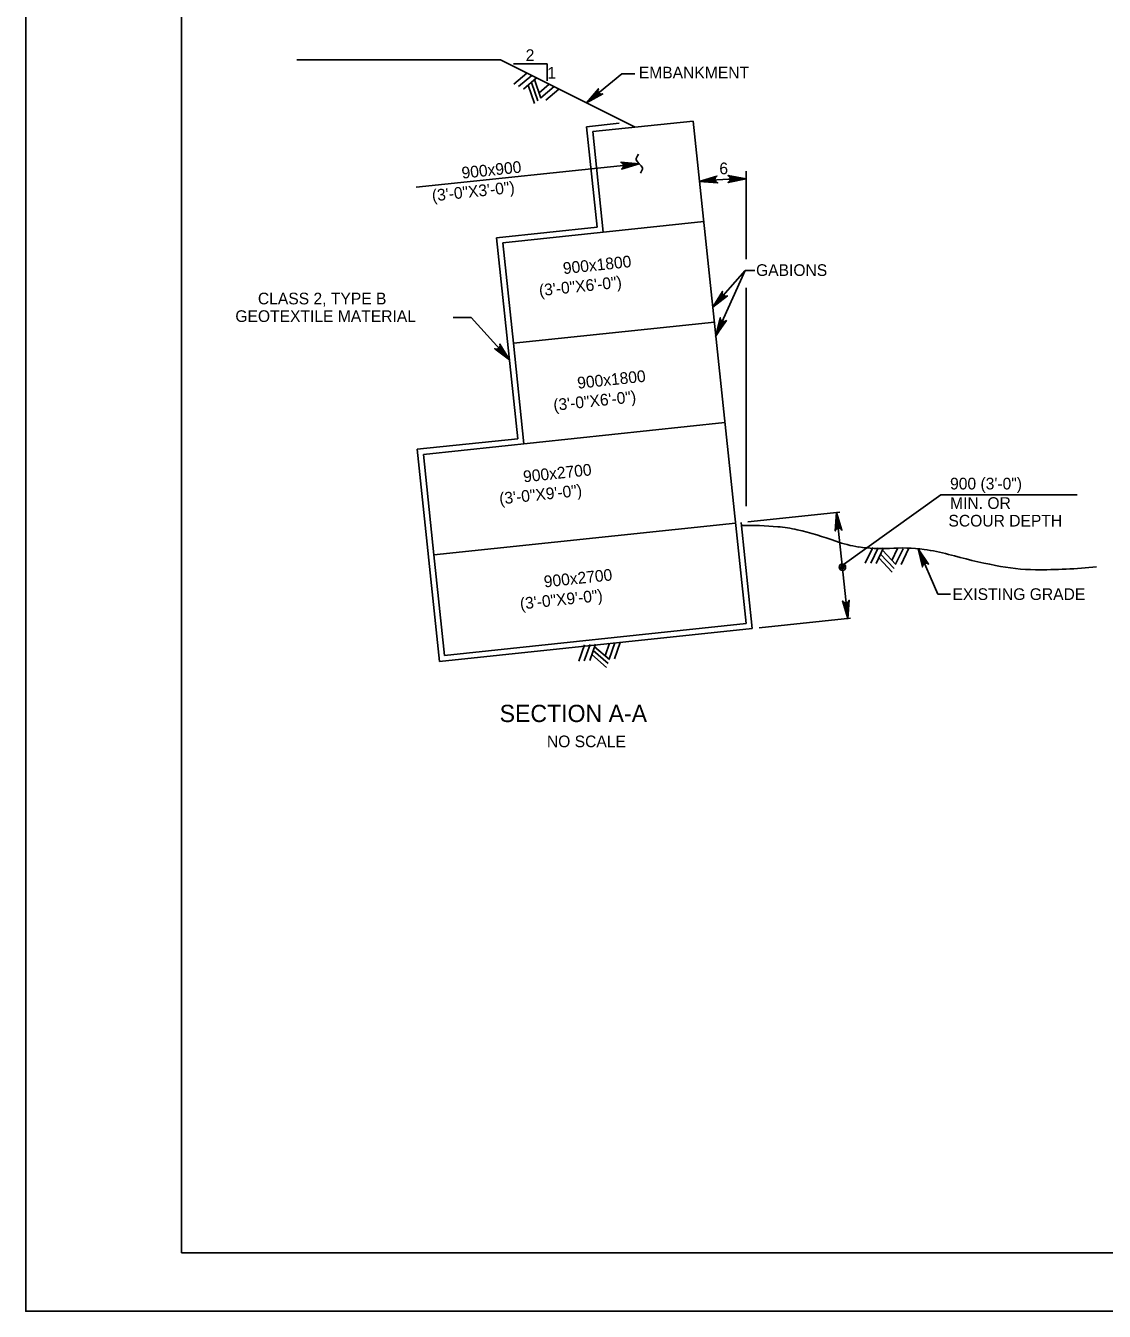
# Model space of a CAD drawing. Extents: x 638142 to 639291, y 297247 to 298438.
# Drawn here: x 638435.5 to 638712.4, y 297247.5 to 297577.6 of the extents above; entities that cross this region are included whole.
import ezdxf

# ---------------------------------------------------------------- set-up
doc = ezdxf.new("R2010")
doc.units = 0
for name, color, linetype in [('2', 7, 'Continuous'), ('3', 7, 'Continuous'), ('5', 7, 'Continuous'), ('PLT-BNDY', 7, 'Continuous')]:
    doc.layers.add(name, color=color, linetype=linetype)

msp = doc.modelspace()

# ---------------------------------------------------------------- linework, layer by layer
at = {"layer": '2'}
for p, q in [((638475.46, 297262.46), (638475.46, 297826.46)), ((639261.46, 297262.46), (638475.46, 297262.46))]:
    msp.add_line(p, q, dxfattribs=at)
at = {"layer": '3'}
for p, q in [((638557.33, 297568.82), (638505.07, 297568.82)), ((638591.93, 297551.51), (638557.33, 297568.82)), ((638564.14, 297565.41), (638560.77, 297562.56)), ((638565.38, 297564.79), (638562.02, 297561.94)), ((638566.63, 297564.17), (638563.26, 297561.31)), ((638565.29, 297563.03), (638566.93, 297558.27)), ((638566.11, 297563.73), (638567.75, 297558.97)), ((638569.86, 297562.55), (638567.27, 297560.35)), ((638564.46, 297562.34), (638566.1, 297557.58)), ((638571.11, 297561.93), (638567.74, 297559.08)), ((638572.35, 297561.3), (638568.99, 297558.45)), ((638581.05, 297550.37), (638606.86, 297553.08)), ((638606.86, 297553.08), (638620.42, 297424.03)), ((638579.46, 297551.65), (638587.87, 297552.54)), ((638582.18, 297525.84), (638579.46, 297551.65)), ((638583.76, 297524.56), (638581.05, 297550.37)), ((638557.95, 297521.85), (638609.57, 297527.27)), ((638556.36, 297523.13), (638582.18, 297525.84)), ((638561.79, 297471.51), (638556.36, 297523.13)), ((638560.66, 297496.04), (638557.95, 297521.85)), ((638560.66, 297496.04), (638612.28, 297501.46)), ((638563.37, 297470.23), (638560.66, 297496.04)), ((638537.57, 297467.51), (638615, 297475.65)), ((638535.98, 297468.8), (638561.79, 297471.51)), ((638541.71, 297414.31), (638535.98, 297468.8)), ((638540.28, 297441.7), (638537.57, 297467.51)), ((638540.28, 297441.7), (638617.71, 297449.84)), ((638619.14, 297449.99), (638622.01, 297422.75)), ((638542.99, 297415.89), (638540.28, 297441.7)), ((638652.92, 297443.58), (638651.03, 297439.6)), ((638654.31, 297443.53), (638652.43, 297439.54)), ((638655.71, 297443.48), (638653.82, 297439.49)), ((638654.49, 297440.91), (638657.94, 297437.26)), ((638654.95, 297441.89), (638658.41, 297438.23)), ((638655.41, 297442.86), (638658.87, 297439.2)), ((638659.32, 297443.34), (638657.86, 297440.27)), ((638660.71, 297443.28), (638658.82, 297439.3)), ((638662.1, 297443.23), (638660.21, 297439.24)), ((638620.42, 297424.03), (638542.99, 297415.89)), ((638622.01, 297422.75), (638541.71, 297414.31)), ((638578.95, 297418.58), (638577.49, 297414.42)), ((638580.34, 297418.67), (638578.88, 297414.51)), ((638581.73, 297418.76), (638580.27, 297414.6)), ((638581.51, 297418.12), (638585.33, 297414.84)), ((638585.34, 297419), (638584.22, 297415.8)), ((638586.73, 297419.09), (638585.27, 297414.93)), ((638588.12, 297419.19), (638586.66, 297415.02)), ((638580.79, 297416.09), (638584.61, 297412.81)), ((638581.15, 297417.1), (638584.97, 297413.83))]:
    msp.add_line(p, q, dxfattribs=at)
for centre, radius, start, end in [((638620.28, 297348.95), 100.32, 85.2758, 90.603), ((638625.74, 297415.01), 34.04, 76.7282, 85.2758), ((638612.28, 297357.94), 92.67, 70.3402, 76.7282), ((638654.33, 297475.65), 32.33, 250.3402, 261.1661), ((638654.89, 297479.25), 35.96, 261.1661, 273.7588), ((638660.24, 297397.8), 45.66, 82.5875, 93.7588), ((638660.15, 297397.12), 46.34, 74.68, 82.5875), ((638718.58, 297610.4), 174.79, 254.68, 258.7493), ((638695.41, 297493.94), 56.06, 258.7493, 269.3013), ((638696.31, 297567.91), 130.03, 269.3013, 276.2239)]:
    msp.add_arc(centre, radius, start, end, dxfattribs=at)
at = {"layer": '5'}
for p, q in [((638569.38, 297567.79), (638560.73, 297567.79)), ((638569.38, 297563.46), (638569.38, 297567.79)), ((638579.44, 297557.76), (638588.53, 297565.19)), ((638588.53, 297565.19), (638591.82, 297565.19)), ((638535.73, 297536.11), (638593, 297542.12)), ((638620.42, 297517.62), (638620.42, 297540.26)), ((638611.88, 297505.3), (638620.22, 297514.68)), ((638612.65, 297497.99), (638620.22, 297514.68)), ((638620.22, 297514.68), (638622.65, 297514.68)), ((638620.42, 297454.16), (638620.42, 297510.3)), ((638549.83, 297502.68), (638545.18, 297502.68)), ((638559.66, 297491.77), (638549.83, 297502.68)), ((638645.11, 297438.95), (638670.4, 297457.12)), ((638670.4, 297457.12), (638705.45, 297457.12)), ((638620.9, 297450.17), (638644.48, 297452.65)), ((638646.54, 297425.33), (638643.67, 297452.57)), ((638664.63, 297443.25), (638669.65, 297431.57)), ((638669.65, 297431.57), (638672.88, 297431.57)), ((638623.76, 297422.93), (638647.26, 297425.4))]:
    msp.add_line(p, q, dxfattribs=at)
for points in [[(638579.44, 297557.76), (638582.49, 297561.39), (638582.37, 297560.97), (638582.43, 297560.61), (638582.58, 297560.33), (638582.82, 297560.13), (638583.16, 297560), (638583.6, 297560.04), (638579.44, 297557.76), (638583.16, 297560), (638582.82, 297560.13), (638579.44, 297557.76), (638582.58, 297560.33), (638582.43, 297560.61), (638579.44, 297557.76), (638582.37, 297560.97)], [(638593, 297542.12), (638588.45, 297540.77), (638588.78, 297541.05), (638588.94, 297541.38), (638588.95, 297541.7), (638588.87, 297542.01), (638588.65, 297542.3), (638588.27, 297542.51), (638593, 297542.12), (638588.65, 297542.3), (638588.87, 297542.01), (638593, 297542.12), (638588.95, 297541.7), (638588.94, 297541.38), (638593, 297542.12), (638588.78, 297541.05)], [(638608.39, 297537.59), (638612.93, 297538.95), (638612.6, 297538.67), (638612.45, 297538.33), (638612.43, 297538.02), (638612.52, 297537.71), (638612.74, 297537.42), (638613.12, 297537.21), (638608.39, 297537.59), (638612.74, 297537.42), (638612.52, 297537.71), (638608.39, 297537.59), (638612.43, 297538.02), (638612.45, 297538.33), (638608.39, 297537.59), (638612.6, 297538.67)], [(638620.47, 297538.23), (638615.8, 297537.35), (638616.16, 297537.6), (638616.35, 297537.92), (638616.4, 297538.23), (638616.35, 297538.54), (638616.16, 297538.85), (638615.81, 297539.1), (638620.47, 297538.23), (638616.16, 297538.85), (638616.35, 297538.54), (638620.47, 297538.23), (638616.4, 297538.23), (638616.35, 297537.92), (638620.47, 297538.23), (638616.16, 297537.6)], [(638611.88, 297505.3), (638614.33, 297509.36), (638614.27, 297508.93), (638614.38, 297508.59), (638614.58, 297508.34), (638614.85, 297508.17), (638615.21, 297508.1), (638615.63, 297508.2), (638611.88, 297505.3), (638615.21, 297508.1), (638614.85, 297508.17), (638611.88, 297505.3), (638614.58, 297508.34), (638614.38, 297508.59), (638611.88, 297505.3), (638614.27, 297508.93)], [(638612.65, 297497.99), (638613.78, 297502.6), (638613.86, 297502.17), (638614.07, 297501.87), (638614.33, 297501.69), (638614.64, 297501.61), (638615, 297501.65), (638615.37, 297501.87), (638612.65, 297497.99), (638615, 297501.65), (638614.64, 297501.61), (638612.65, 297497.99), (638614.33, 297501.69), (638614.07, 297501.87), (638612.65, 297497.99), (638613.86, 297502.17)], [(638559.66, 297491.77), (638555.89, 297494.64), (638556.32, 297494.54), (638556.67, 297494.62), (638556.94, 297494.78), (638557.14, 297495.03), (638557.25, 297495.38), (638557.19, 297495.81), (638559.66, 297491.77), (638557.25, 297495.38), (638557.14, 297495.03), (638559.66, 297491.77), (638556.94, 297494.78), (638556.67, 297494.62), (638559.66, 297491.77), (638556.32, 297494.54)], [(638643.67, 297452.57), (638645.03, 297448.03), (638644.75, 297448.36), (638644.42, 297448.51), (638644.1, 297448.53), (638643.79, 297448.44), (638643.5, 297448.23), (638643.29, 297447.84), (638643.67, 297452.57), (638643.5, 297448.23), (638643.79, 297448.44), (638643.67, 297452.57), (638644.1, 297448.53), (638644.42, 297448.51), (638643.67, 297452.57), (638644.75, 297448.36)], [(638664.63, 297443.25), (638667.28, 297439.31), (638666.91, 297439.54), (638666.55, 297439.59), (638666.24, 297439.52), (638665.97, 297439.34), (638665.76, 297439.05), (638665.67, 297438.62), (638664.63, 297443.25), (638665.76, 297439.05), (638665.97, 297439.34), (638664.63, 297443.25), (638666.24, 297439.52), (638666.55, 297439.59), (638664.63, 297443.25), (638666.91, 297439.54)], [(638646.54, 297425.33), (638645.18, 297429.87), (638645.47, 297429.54), (638645.8, 297429.39), (638646.11, 297429.36), (638646.42, 297429.45), (638646.71, 297429.67), (638646.92, 297430.05), (638646.54, 297425.33), (638646.71, 297429.67), (638646.42, 297429.45), (638646.54, 297425.33), (638646.11, 297429.36), (638645.8, 297429.39), (638646.54, 297425.33), (638645.47, 297429.54)]]:
    msp.add_lwpolyline(points, dxfattribs=at)
for points in [[(638581.98, 297559.21), (638581.37, 297559.96), (638579.44, 297557.76)], [(638611.4, 297537.39), (638611.31, 297538.34), (638608.49, 297537.6)], [(638617.55, 297537.71), (638617.53, 297538.67), (638620.42, 297538.23)], [(638614.16, 297507.14), (638613.44, 297507.78), (638611.88, 297505.3)], [(638614.2, 297500.24), (638613.32, 297500.63), (638612.57, 297497.81)], [(638557.99, 297494.33), (638557.28, 297493.69), (638559.57, 297491.87)], [(638643.5, 297449.65), (638644.45, 297449.75), (638643.67, 297452.57)], [(638665.33, 297440.41), (638666.21, 297440.79), (638664.64, 297443.25)], [(638645.76, 297428.14), (638646.71, 297428.24), (638646.54, 297425.33)]]:
    msp.add_lwpolyline(points, close=True, dxfattribs=at)
for radius in [0.833, 0.417]:
    msp.add_circle((638645.15, 297438.56), radius, dxfattribs=at)
msp.add_arc((638620.42, 297424.03), 114.2, 89.9783, 96.0478, dxfattribs=at)
msp.add_spline([(638592.79, 297544.55), (638592.22, 297543.13), (638593.79, 297541.1), (638593.28, 297539.71)], degree=3, dxfattribs=at)
at = {"layer": 'PLT-BNDY'}
msp.add_lwpolyline([(638435.46, 297841.46), (639276.46, 297841.46), (639276.46, 297247.46), (638435.46, 297247.46)], close=True, dxfattribs=at)

# ---------------------------------------------------------------- texts
at = {"layer": '5'}
for s, height, p in [('2', 3, (638563.83, 297568.52)), ('1', 3, (638569.38, 297563.98)), ('EMBANKMENT', 3, (638592.87, 297564.04)), ('6', 3, (638613.55, 297539.43)), ('GABIONS', 3, (638622.97, 297513.32)), ('CLASS 2, TYPE B', 3.0001, (638495.07, 297506.02)), ('GEOTEXTILE MATERIAL', 3.0001, (638489.28, 297501.5)), ('900 (3\'-0")', 3.0001, (638672.79, 297458.5)), ('MIN. OR', 3, (638672.79, 297453.5)), ('SCOUR DEPTH', 3.0001, (638672.37, 297448.97)), ('EXISTING GRADE', 3.0001, (638673.4, 297430.11)), ('SECTION A-A', 4.4294, (638557.14, 297398.76)), ('NO SCALE', 3, (638569.27, 297392.3))]:
    msp.add_text(s, height=height, dxfattribs=at).set_placement(p)
for s, height, p in [('900x900', 3, (638547.53, 297538.28)), ('(3\'-0"X3\'-0")', 3.0001, (638539.91, 297532.45)), ('900x1800', 3, (638573.55, 297513.78)), ('(3\'-0"X6\'-0")', 3.0001, (638567.41, 297508.11)), ('900x1800', 3, (638577.23, 297484.34)), ('(3\'-0"X6\'-0")', 3.0001, (638571.09, 297478.67)), ('900x2700', 3, (638563.34, 297460.3)), ('(3\'-0"X9\'-0")', 3.0001, (638557.2, 297454.63)), ('900x2700', 3, (638568.65, 297433.32)), ('(3\'-0"X9\'-0")', 3.0001, (638562.51, 297427.65))]:
    msp.add_text(s, height=height, rotation=6, dxfattribs=at).set_placement(p)

doc.saveas('drawing.dxf')
